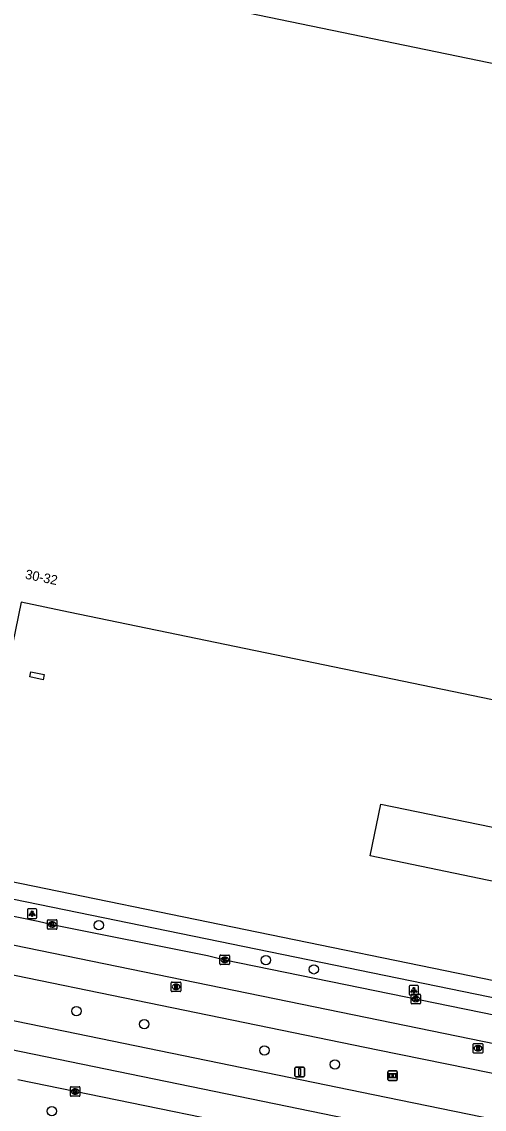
# Model space of a CAD drawing. Extents: x 157692 to 159670, y 381454 to 383289.
# Drawn here: x 158105.1 to 158153.7, y 382186.1 to 382300.3 of the extents above; entities that cross this region are included whole.
import ezdxf

# ---------------------------------------------------------------- set-up
doc = ezdxf.new("R2010")
doc.units = 0
for name, color, linetype in [('IMGEO_Boom', 7, 'Continuous'), ('IMGEO_Informatiebord', 7, 'Continuous'), ('IMGEO_Kolk', 7, 'Continuous'), ('IMGEO_Lichtpunt', 7, 'Continuous'), ('IMGEO_Pand', 7, 'Continuous'), ('IMGEO_Pand_nummerreeks', 7, 'Continuous'), ('IMGEO_Rijbaan_regionaal_gesloten', 7, 'Continuous'), ('IMGEO_Rioolput', 7, 'Continuous'), ('IMGEO_Verkeersbordpaal', 7, 'Continuous'), ('IMGEO_Voetpad_open', 7, 'Continuous')]:
    doc.layers.add(name, color=color, linetype=linetype)

msp = doc.modelspace()

# ---------------------------------------------------------------- linework, layer by layer
at = {"layer": 'IMGEO_Boom'}
for centre in [(158113.16, 382205.39), (158130.73, 382201.73), (158135.77, 382200.76), (158110.81, 382196.37), (158117.94, 382195), (158130.58, 382192.24), (158137.99, 382190.77), (158108.22, 382185.86)]:
    msp.add_circle(centre, 0.489, dxfattribs=at)
at = {"layer": 'IMGEO_Informatiebord'}
for p, q in [((158143.56, 382189.19), (158143.56, 382189.99)), ((158143.56, 382189.99), (158143.56, 382189.19)), ((158143.66, 382190.09), (158144.45, 382190.09)), ((158144.45, 382190.09), (158143.66, 382190.09)), ((158144.55, 382189.99), (158144.55, 382189.19)), ((158144.55, 382189.19), (158144.55, 382189.99)), ((158144.45, 382189.09), (158143.66, 382189.09)), ((158143.66, 382189.09), (158144.45, 382189.09))]:
    msp.add_line(p, q, dxfattribs=at)
for points in [[(158143.66, 382189.82), (158144.45, 382189.82), (158144.45, 382189.35), (158143.66, 382189.35), (158143.66, 382189.82)], [(158143.72, 382189.75), (158143.72, 382189.42), (158144, 382189.42), (158144, 382189.63), (158144.1, 382189.63), (158144.11, 382189.42), (158144.38, 382189.42), (158144.38, 382189.75), (158144.11, 382189.75), (158144.11, 382189.67), (158144, 382189.67), (158144, 382189.75), (158143.72, 382189.75)]]:
    msp.add_lwpolyline(points, dxfattribs=at)
for centre, start, end in [((158143.66, 382189.99), 90, 180), ((158143.66, 382189.99), 90, 180), ((158144.45, 382189.99), 0, 90), ((158144.45, 382189.99), 360, 90), ((158143.66, 382189.19), 180, 270), ((158143.66, 382189.19), 180, 270), ((158144.45, 382189.19), 270, 0), ((158144.45, 382189.19), 270, 0)]:
    msp.add_arc(centre, 0.1, start, end, dxfattribs=at)
at = {"layer": 'IMGEO_Kolk'}
for p, q in [((158107.76, 382205.05), (158107.76, 382205.91)), ((158107.83, 382205.98), (158108.69, 382205.98)), ((158108.25, 382205.76), (158108.27, 382205.76)), ((158108.76, 382205.91), (158108.76, 382205.05)), ((158108.69, 382204.98), (158107.83, 382204.98)), ((158108.27, 382205.2), (158108.24, 382205.2)), ((158125.9, 382201.33), (158125.9, 382202.19)), ((158125.97, 382202.26), (158126.83, 382202.26)), ((158126.9, 382202.19), (158126.9, 382201.33)), ((158126.83, 382201.26), (158125.97, 382201.26)), ((158126.41, 382201.48), (158126.38, 382201.48)), ((158126.39, 382202.04), (158126.41, 382202.04)), ((158146, 382197.21), (158146, 382198.06)), ((158146.07, 382198.14), (158146.93, 382198.14)), ((158146.49, 382197.92), (158146.51, 382197.92)), ((158147, 382198.06), (158147, 382197.21)), ((158146.93, 382197.14), (158146.07, 382197.14)), ((158146.51, 382197.36), (158146.48, 382197.36)), ((158110.17, 382187.5), (158110.17, 382188.35)), ((158110.25, 382188.42), (158111.1, 382188.42)), ((158111.1, 382187.42), (158110.25, 382187.42)), ((158110.66, 382188.2), (158110.69, 382188.2)), ((158110.68, 382187.64), (158110.66, 382187.64)), ((158111.18, 382188.35), (158111.18, 382187.5))]:
    msp.add_line(p, q, dxfattribs=at)
for points in [[(158107.76, 382205.05), (158107.76, 382205.91)], [(158107.83, 382205.98), (158108.69, 382205.98)], [(158108.08, 382205.68), (158108.2, 382205.68), (158108.2, 382205.53), (158108.33, 382205.68), (158108.5, 382205.68), (158108.35, 382205.53), (158108.5, 382205.28), (158108.35, 382205.28), (158108.27, 382205.44), (158108.2, 382205.38), (158108.2, 382205.28), (158108.08, 382205.28), (158108.08, 382205.68)], [(158108.76, 382205.91), (158108.76, 382205.05)], [(158108.69, 382204.98), (158107.83, 382204.98)], [(158125.9, 382201.33), (158125.9, 382202.19)], [(158125.97, 382202.26), (158126.83, 382202.26)], [(158126.9, 382202.19), (158126.9, 382201.33)], [(158126.83, 382201.26), (158125.97, 382201.26)], [(158126.22, 382201.96), (158126.34, 382201.96), (158126.34, 382201.81), (158126.47, 382201.96), (158126.64, 382201.96), (158126.49, 382201.81), (158126.64, 382201.56), (158126.49, 382201.56), (158126.41, 382201.73), (158126.34, 382201.66), (158126.34, 382201.56), (158126.22, 382201.56), (158126.22, 382201.96)], [(158146, 382197.21), (158146, 382198.06)], [(158146.07, 382198.14), (158146.93, 382198.14)], [(158146.32, 382197.84), (158146.44, 382197.84), (158146.44, 382197.69), (158146.57, 382197.84), (158146.74, 382197.84), (158146.59, 382197.69), (158146.74, 382197.44), (158146.59, 382197.44), (158146.51, 382197.6), (158146.44, 382197.54), (158146.44, 382197.44), (158146.32, 382197.44), (158146.32, 382197.84)], [(158147, 382198.06), (158147, 382197.21)], [(158146.93, 382197.14), (158146.07, 382197.14)], [(158110.17, 382187.5), (158110.17, 382188.35)], [(158110.25, 382188.42), (158111.1, 382188.42)], [(158111.1, 382187.42), (158110.25, 382187.42)], [(158110.49, 382188.12), (158110.62, 382188.12), (158110.62, 382187.97), (158110.75, 382188.12), (158110.91, 382188.12), (158110.77, 382187.97), (158110.92, 382187.72), (158110.77, 382187.72), (158110.68, 382187.89), (158110.62, 382187.82), (158110.62, 382187.72), (158110.49, 382187.72), (158110.49, 382188.12)], [(158111.18, 382188.35), (158111.18, 382187.5)]]:
    msp.add_lwpolyline(points, dxfattribs=at)
for centre, start, end in [((158107.84, 382205.9), 91.552, 178.448), ((158107.84, 382205.9), 91.552, 178.448), ((158108.68, 382205.9), 1.552, 88.448), ((158108.68, 382205.9), 1.552, 88.448), ((158107.84, 382205.05), 181.552, 268.448), ((158107.84, 382205.05), 181.552, 268.448), ((158108.68, 382205.05), 271.552, 358.448), ((158108.68, 382205.05), 271.552, 358.448), ((158125.98, 382202.19), 91.552, 178.448), ((158125.98, 382202.19), 91.552, 178.448), ((158126.82, 382202.19), 1.552, 88.448), ((158126.82, 382202.19), 1.552, 88.448), ((158125.98, 382201.34), 181.552, 268.448), ((158125.98, 382201.34), 181.552, 268.448), ((158126.82, 382201.34), 271.552, 358.448), ((158126.82, 382201.34), 271.552, 358.448), ((158146.07, 382198.06), 91.552, 178.448), ((158146.07, 382198.06), 91.552, 178.448), ((158146.92, 382198.06), 1.552, 88.448), ((158146.92, 382198.06), 1.552, 88.448), ((158146.07, 382197.21), 181.552, 268.448), ((158146.07, 382197.21), 181.552, 268.448), ((158146.92, 382197.21), 271.552, 358.448), ((158146.92, 382197.21), 271.552, 358.448), ((158110.25, 382188.35), 91.552, 178.448), ((158110.25, 382188.35), 91.552, 178.448), ((158110.25, 382187.5), 181.552, 268.448), ((158110.25, 382187.5), 181.552, 268.448), ((158111.1, 382188.35), 1.552, 88.448), ((158111.1, 382188.35), 1.552, 88.448), ((158111.1, 382187.5), 271.552, 358.448), ((158111.1, 382187.5), 271.552, 358.448)]:
    msp.add_arc(centre, 0.0765, start, end, dxfattribs=at)
for centre, major_axis, ratio, start_param, end_param in [((158108.25, 382205.48), (-0.387, 0.002), 0.722429, 4.712389, 7.853982), ((158108.27, 382205.48), (-0.39, 0.002), 0.717154, 1.570796, 4.712389), ((158126.39, 382201.76), (-0.387, 0.002), 0.722429, 4.712389, 7.853982), ((158126.41, 382201.76), (-0.39, 0.002), 0.717154, 1.570796, 4.712389), ((158146.49, 382197.64), (-0.387, 0.002), 0.722429, 4.712389, 7.853982), ((158146.51, 382197.64), (-0.39, 0.002), 0.717154, 1.570796, 4.712389), ((158110.66, 382187.92), (-0.387, 0.002), 0.722429, 4.712389, 7.853982), ((158110.69, 382187.92), (-0.39, 0.002), 0.717154, 1.570796, 4.712389)]:
    msp.add_ellipse(centre, major_axis=major_axis, ratio=ratio, start_param=start_param, end_param=end_param, dxfattribs=at)
at = {"layer": 'IMGEO_Lichtpunt'}
for p, q in [((158105.65, 382207.03), (158105.65, 382206.22)), ((158105.65, 382207.03), (158105.65, 382206.22)), ((158106.55, 382207.12), (158105.74, 382207.12)), ((158106.55, 382207.12), (158105.74, 382207.12)), ((158106.64, 382206.22), (158106.64, 382207.03)), ((158106.64, 382206.22), (158106.64, 382207.03)), ((158105.74, 382206.12), (158106.55, 382206.12)), ((158105.74, 382206.12), (158106.55, 382206.12)), ((158145.78, 382198.97), (158145.78, 382198.16)), ((158145.78, 382198.97), (158145.78, 382198.16)), ((158146.69, 382199.07), (158145.88, 382199.07)), ((158146.69, 382199.07), (158145.88, 382199.07)), ((158146.78, 382198.16), (158146.78, 382198.97)), ((158146.78, 382198.16), (158146.78, 382198.97)), ((158145.88, 382198.07), (158146.69, 382198.07)), ((158145.88, 382198.07), (158146.69, 382198.07))]:
    msp.add_line(p, q, dxfattribs=at)
for points in [[(158106.02, 382206.69), (158106.06, 382206.66), (158105.87, 382206.4), (158105.83, 382206.43), (158106.02, 382206.69)], [(158106.12, 382206.64), (158106.17, 382206.64), (158106.17, 382206.32), (158106.12, 382206.32), (158106.12, 382206.64)], [(158106.23, 382206.66), (158106.27, 382206.69), (158106.46, 382206.43), (158106.42, 382206.4), (158106.23, 382206.66)], [(158146.16, 382198.63), (158146.2, 382198.61), (158146.01, 382198.34), (158145.97, 382198.37), (158146.16, 382198.63)], [(158146.26, 382198.59), (158146.31, 382198.59), (158146.31, 382198.26), (158146.26, 382198.26), (158146.26, 382198.59)], [(158146.37, 382198.61), (158146.41, 382198.63), (158146.59, 382198.37), (158146.56, 382198.34), (158146.37, 382198.61)]]:
    msp.add_lwpolyline(points, dxfattribs=at)
for centre in [(158106.15, 382206.82), (158146.28, 382198.77)]:
    msp.add_circle(centre, 0.0994, dxfattribs=at)
for centre, start, end in [((158105.74, 382207.03), 90, 180), ((158105.74, 382207.03), 90, 180), ((158106.55, 382207.03), 0, 90), ((158106.55, 382207.03), 0, 90), ((158105.74, 382206.22), 180, 270), ((158105.74, 382206.22), 180, 270), ((158106.55, 382206.22), 270, 0), ((158106.55, 382206.22), 270, 360), ((158145.88, 382198.97), 90, 180), ((158145.88, 382198.97), 90, 180), ((158146.69, 382198.97), 0, 90), ((158146.69, 382198.97), 0, 90), ((158145.88, 382198.16), 180, 270), ((158145.88, 382198.16), 180, 270), ((158146.69, 382198.16), 270, 0), ((158146.69, 382198.16), 270, 360)]:
    msp.add_arc(centre, 0.0946, start, end, dxfattribs=at)
at = {"layer": 'IMGEO_Pand'}
for points in [[(158191.55, 382288.32), (158183.63, 382250), (158178.3, 382224.18), (158109.97, 382238.3), (158105, 382239.32), (158103.5, 382231.98), (158081.67, 382236.49), (158081.85, 382237.37), (158078.93, 382237.98), (158078.68, 382236.85), (158053.51, 382242.03), (158053.56, 382242.29), (158042.93, 382244.5), (158044.57, 382252.45), (158045.53, 382257.07), (158056.12, 382254.86), (158068.35, 382313.75), (158191.55, 382288.32)], [(158107.41, 382231.72), (158107.3, 382231.19), (158105.89, 382231.49), (158106, 382232.01), (158107.41, 382231.72)], [(158156.98, 382215.2), (158155.85, 382209.76), (158141.68, 382212.69), (158142.81, 382218.13), (158156.98, 382215.2)]]:
    msp.add_lwpolyline(points, dxfattribs=at)
at = {"layer": 'IMGEO_Rijbaan_regionaal_gesloten'}
for points in [[(158343.52, 382152.53), (158327.52, 382155.49), (158318.89, 382157.28), (158300.1, 382161.18), (158268.72, 382167.57), (158256.93, 382170), (158249.1, 382171.7), (158237.46, 382174.56), (158225.89, 382177.69), (158214.46, 382180.53), (158188.03, 382186.1), (157930.79, 382238.81)], [(157925.24, 382226.65), (157933.19, 382224.57), (157944.25, 382221.93), (157952.27, 382220.28), (157960.71, 382218.53), (157972.66, 382216.32), (157984.66, 382214.3), (157988.35, 382213.71), (157992.78, 382213.1), (157996.27, 382212.62), (158008.57, 382210.94), (158012.61, 382210.39), (158016.65, 382209.74), (158020.14, 382209.23), (158024.23, 382208.5), (158031.47, 382207.21), (158206.47, 382171.3), (158336.06, 382144.82)], [(158012.83, 382218.93), (158142.51, 382192.31), (158170.98, 382186.52), (158185.71, 382183.48), (158196.08, 382181.33)], [(158032.03, 382210.19), (158142.01, 382187.62), (158169.03, 382182.07), (158195.17, 382176.73)], [(158099.18, 382207.37), (158106.8, 382205.83), (158108.26, 382205.48), (158124.58, 382202.21), (158126.4, 382201.76), (158169.11, 382193.04), (158184.7, 382189.79), (158187.86, 382189.16), (158188.22, 382189.09)], [(158138.88, 382182.14), (158104.65, 382189.16)]]:
    msp.add_lwpolyline(points, dxfattribs=at)
at = {"layer": 'IMGEO_Rioolput'}
for p, q in [((158120.78, 382198.5), (158120.78, 382199.35)), ((158120.85, 382199.43), (158121.71, 382199.43)), ((158121.27, 382199.21), (158121.29, 382199.21)), ((158121.78, 382199.35), (158121.78, 382198.5)), ((158121.71, 382198.43), (158120.85, 382198.43)), ((158121.29, 382198.65), (158121.26, 382198.65)), ((158152.54, 382192.04), (158152.54, 382192.89)), ((158152.61, 382192.97), (158153.46, 382192.97)), ((158153.46, 382191.97), (158152.61, 382191.97)), ((158153.02, 382192.75), (158153.05, 382192.75)), ((158153.05, 382192.19), (158153.02, 382192.19)), ((158153.54, 382192.89), (158153.54, 382192.04))]:
    msp.add_line(p, q, dxfattribs=at)
for points in [[(158120.78, 382198.5), (158120.78, 382199.35)], [(158120.85, 382199.43), (158121.71, 382199.43)], [(158121.37, 382199.12), (158121.12, 382199.13), (158121.12, 382198.73)], [(158121.12, 382198.73), (158121.24, 382198.73), (158121.24, 382198.89), (158121.25, 382198.89)], [(158121.29, 382199.05), (158121.24, 382199.05), (158121.24, 382198.96)], [(158121.24, 382198.96), (158121.29, 382198.96)], [(158121.3, 382198.86), (158121.37, 382198.73), (158121.51, 382198.73), (158121.44, 382198.85)], [(158121.78, 382199.35), (158121.78, 382198.5)], [(158121.71, 382198.43), (158120.85, 382198.43)], [(158152.54, 382192.04), (158152.54, 382192.89)], [(158152.61, 382192.97), (158153.46, 382192.97)], [(158153.46, 382191.97), (158152.61, 382191.97)], [(158153.12, 382192.66), (158152.87, 382192.67), (158152.87, 382192.27)], [(158152.87, 382192.27), (158153, 382192.27), (158153, 382192.43), (158153.01, 382192.43)], [(158153.05, 382192.59), (158153, 382192.59), (158153, 382192.5)], [(158153, 382192.5), (158153.05, 382192.5)], [(158153.05, 382192.4), (158153.13, 382192.27), (158153.26, 382192.27), (158153.2, 382192.39)], [(158153.54, 382192.89), (158153.54, 382192.04)]]:
    msp.add_lwpolyline(points, dxfattribs=at)
for centre, radius, start, end in [((158120.86, 382199.35), 0.0765, 91.552, 178.448), ((158120.86, 382199.35), 0.0765, 91.552, 178.448), ((158121.25, 382198.84), 0.0533, 26.0293, 88.6989), ((158121.3, 382198.95), 0.0964, 77.0061, 93.1865), ((158121.28, 382199.15), 0.19, 274.7715, 282.9687), ((158121.31, 382199.01), 0.0378, 276.6634, 79.6772), ((158121.37, 382199.02), 0.109, 350.3612, 89.416), ((158121.37, 382199.01), 0.112, 277.5842, 350.9817), ((158121.35, 382198.8), 0.108, 29.5134, 73.7905), ((158121.7, 382199.35), 0.0765, 1.552, 88.448), ((158121.7, 382199.35), 0.0765, 1.552, 88.448), ((158120.86, 382198.5), 0.0765, 181.552, 268.448), ((158120.86, 382198.5), 0.0765, 181.552, 268.448), ((158121.7, 382198.5), 0.0765, 271.552, 358.448), ((158121.7, 382198.5), 0.0765, 271.552, 358.448), ((158152.61, 382192.89), 0.0765, 91.552, 178.448), ((158152.61, 382192.89), 0.0765, 91.552, 178.448), ((158152.61, 382192.04), 0.0765, 181.552, 268.448), ((158152.61, 382192.04), 0.0765, 181.552, 268.448), ((158153.01, 382192.38), 0.0533, 26.0293, 88.6989), ((158153.06, 382192.49), 0.0964, 77.0061, 93.1865), ((158153.03, 382192.69), 0.19, 274.7715, 282.9687), ((158153.07, 382192.55), 0.0378, 276.6634, 79.6772), ((158153.12, 382192.55), 0.109, 350.3612, 89.416), ((158153.12, 382192.55), 0.112, 277.5842, 350.9817), ((158153.11, 382192.34), 0.108, 29.5134, 73.7905), ((158153.46, 382192.89), 0.0765, 1.552, 88.448), ((158153.46, 382192.89), 0.0765, 1.552, 88.448), ((158153.46, 382192.04), 0.0765, 271.552, 358.448), ((158153.46, 382192.04), 0.0765, 271.552, 358.448)]:
    msp.add_arc(centre, radius, start, end, dxfattribs=at)
for centre, major_axis, ratio, start_param, end_param in [((158121.27, 382198.93), (-0.387, 0.002), 0.722429, 4.712389, 7.853982), ((158121.29, 382198.93), (-0.39, 0.002), 0.717154, 1.570796, 4.712389), ((158153.02, 382192.47), (-0.387, 0.002), 0.722429, 4.712389, 7.853982), ((158153.05, 382192.47), (-0.39, 0.002), 0.717154, 1.570796, 4.712389)]:
    msp.add_ellipse(centre, major_axis=major_axis, ratio=ratio, start_param=start_param, end_param=end_param, dxfattribs=at)
at = {"layer": 'IMGEO_Verkeersbordpaal'}
for p, q in [((158133.79, 382189.57), (158133.79, 382190.37)), ((158133.79, 382190.37), (158133.79, 382189.57)), ((158133.89, 382190.47), (158134.68, 382190.47)), ((158134.68, 382190.47), (158133.89, 382190.47)), ((158134.78, 382190.37), (158134.78, 382189.57)), ((158134.78, 382189.57), (158134.78, 382190.37)), ((158134.68, 382189.47), (158133.89, 382189.47)), ((158133.89, 382189.47), (158134.68, 382189.47))]:
    msp.add_line(p, q, dxfattribs=at)
msp.add_lwpolyline([(158134.21, 382190.35), (158134.36, 382190.35), (158134.36, 382189.6), (158134.21, 382189.6), (158134.21, 382190.35)], dxfattribs=at)
for centre, start, end in [((158133.89, 382190.37), 90, 180), ((158133.89, 382190.37), 90, 180), ((158134.68, 382190.37), 0, 90), ((158134.68, 382190.37), 360, 90), ((158133.89, 382189.57), 180, 270), ((158133.89, 382189.57), 180, 270), ((158134.68, 382189.57), 270, 0), ((158134.68, 382189.57), 270, 0)]:
    msp.add_arc(centre, 0.1, start, end, dxfattribs=at)
at = {"layer": 'IMGEO_Voetpad_open'}
for points in [[(158193.23, 382189.84), (158101.45, 382208.65), (158076.4, 382220.19), (157938.83, 382248.42), (157937.52, 382249.29)], [(158103.67, 382210.06), (158178.42, 382194.72), (158193.12, 382191.69)]]:
    msp.add_lwpolyline(points, dxfattribs=at)

# ---------------------------------------------------------------- texts
at = {"layer": 'IMGEO_Pand_nummerreeks'}
msp.add_text('30-32', height=1, rotation=348.4728, dxfattribs=at).set_placement((158105.36, 382241.81))

doc.saveas('drawing.dxf')
